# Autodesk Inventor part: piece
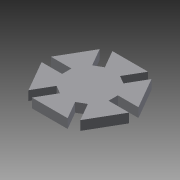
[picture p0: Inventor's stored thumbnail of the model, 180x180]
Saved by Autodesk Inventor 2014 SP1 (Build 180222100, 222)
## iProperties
Created: 2015-02
Part Number: piece
Material: Generic
Document SubType Name: Modeling
Designer: Mohamed
Density: 1 g/cm^3
Appearance: Default
Author: Mohamed
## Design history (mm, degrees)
sketch "Sketch1"
  geometry: 1 further point
sketch "Sketch2"
  geometry: L1 (-8.366, -11.49)-(-14.134, -1.5); L2 (-14.134, 1.5)-(-8.366, 11.49); L3 (-5.768, 12.99)-(5.768, 12.99); L4 (8.366, 11.49)-(14.134, 1.5); L5 (14.134, -1.5)-(8.366, -11.49); L6 (5.768, -12.99)-(-5.768, -12.99); L7 (7.5, 12.99)-(-7.5, -12.99); L8 (11.25, -6.495)-(-11.25, 6.495); L9 (3.75, 6.495)-(5.049, 5.745); L10 (5.049, 5.745)-(8.366, 11.49); L11 (2.451, 7.245)-(5.768, 12.99); L12 (3.75, 6.495)-(2.451, 7.245); L13 (-2.451, 7.245)-(-5.768, 12.99); L14 (-3.75, 6.495)-(-2.451, 7.245); L15 (-3.75, 6.495)-(-5.049, 5.745); L16 (-5.049, 5.745)-(-8.366, 11.49); L17 (-7.5, 1.5)-(-14.134, 1.5); L18 (-7.5, 0)-(-7.5, 1.5); L19 (-7.5, 0)-(-7.5, -1.5); L20 (-7.5, -1.5)-(-14.134, -1.5); L21 (-5.049, -5.745)-(-8.366, -11.49); L22 (-3.75, -6.495)-(-5.049, -5.745); L23 (-3.75, -6.495)-(-2.451, -7.245); L24 (-2.451, -7.245)-(-5.768, -12.99); L25 (2.451, -7.245)-(5.768, -12.99); L26 (3.75, -6.495)-(2.451, -7.245); L27 (3.75, -6.495)-(5.049, -5.745); L28 (5.049, -5.745)-(8.366, -11.49); L29 (7.5, -1.5)-(14.134, -1.5); L30 (7.5, 0)-(7.5, -1.5); L31 (7.5, 0)-(7.5, 1.5); L32 (7.5, 1.5)-(14.134, 1.5); 2 further points
  constraints: 64 end point, 2 midpoint, 2 parallel, 2 point on line, 2 symmetric about line, 1 coincident, 1 horizontal, 1 perpendicular, 62 other
  dimensions: "d3" = 7.5 distance of L9.start L7.start (= 0.25 x ploygon_diameter); "d4" = 1.5 distance of L9.start L9.end; "ploygon_diameter" = 30 distance of L7.start L7.end; "d8" = 360 deg dimension on point (0, 0) L9.end (derived)
extrude "Extrusion1" new body sketch "Sketch2" distance "d0" = 3; taper "d1" = 0 deg
body "Solid1"
other parameters: "polygon_length" = 15
